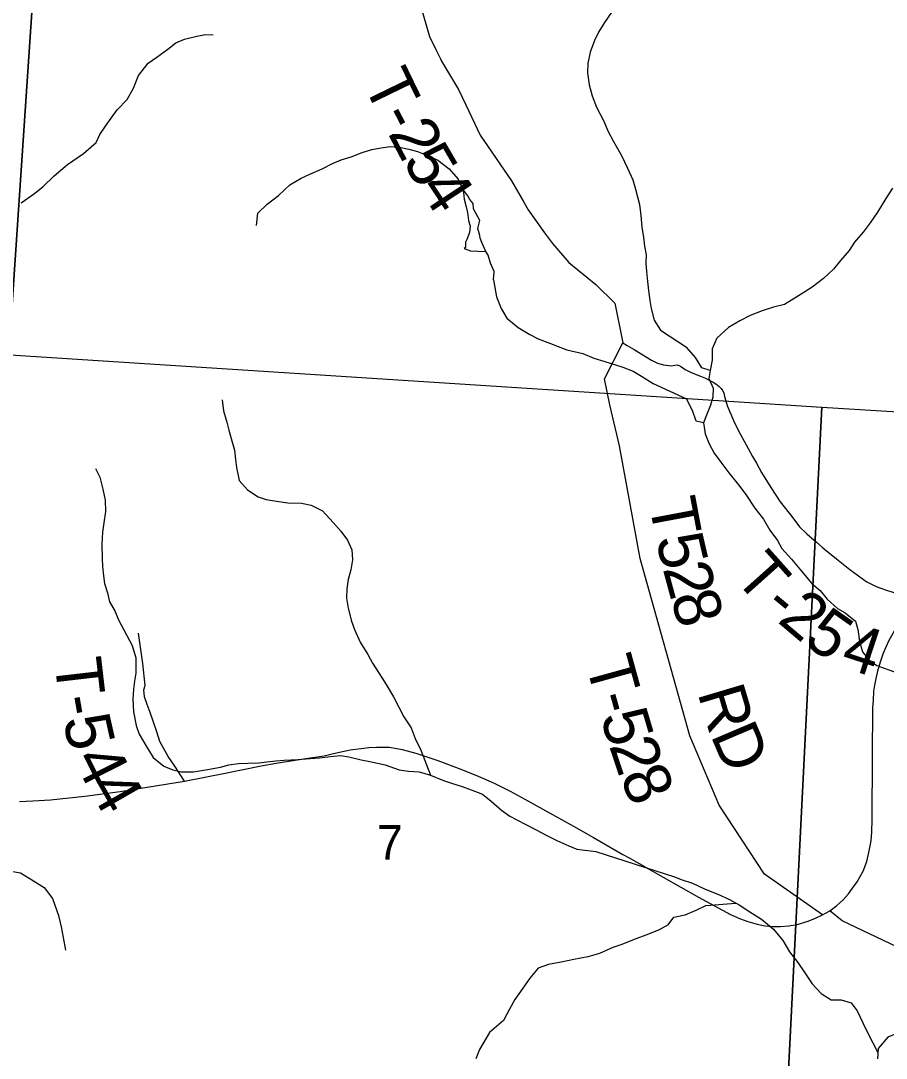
# Model space of a CAD drawing. Extents: x 0 to 44, y -23.8 to 22.
# Drawn here: x 3.565 to 4.614, y 18.843 to 20.101 of the extents above; entities that cross this region are included whole.
import ezdxf

# ---------------------------------------------------------------- set-up
doc = ezdxf.new("R2010")
doc.units = 0
for name, color, linetype in [('Default', 7, 'Continuous'), ('GM_X_Minor_Lake', 7, 'Continuous'), ('GM_X_Minor_River', 7, 'Continuous'), ('GM_X_Section', 7, 'Continuous'), ('GM_X_Section_Text', 7, 'Continuous'), ('GM_X_State_Route', 7, 'Continuous'), ('GM_X_Township_Road', 7, 'Continuous'), ('GM_X_Township_Road_Text', 7, 'Continuous'), ('SH_Cut_Line', 7, 'Continuous')]:
    doc.layers.add(name, color=color, linetype=linetype)

msp = doc.modelspace()

# ---------------------------------------------------------------- linework, layer by layer
at = {"layer": 'Default'}
msp.add_lwpolyline([(6.8158, 20.9), (2.3497, 20.9), (2.472, 20.6113), (2.8013, 19.8369), (3.0092, 19.3427), (3.0496, 19.2474), (3.1321, 19.0527), (3.1789, 18.9421), (3.455, 18.29), (3.5135, 19.1552), (3.5139, 19.1608), (3.5639, 19.9016), (3.5995, 20.4294), (3.5996, 20.4304), (3.6002, 20.4391), (3.6191, 20.7184), (3.9141, 20.6975), (4.3639, 20.6657), (6.7023, 20.5094), (6.7107, 20.5383)], close=True, dxfattribs=at)
msp.add_lwpolyline([(7.4495, 20.4611), (7.016, 20.4891), (6.892, 20.4972), (6.8124, 20.5023), (6.7257, 20.5079), (6.7023, 20.5094), (4.3639, 20.6657), (3.9141, 20.6975), (3.6191, 20.7184), (3.6002, 20.4391), (3.5996, 20.4304), (3.5995, 20.4294), (3.5639, 19.9016), (3.5139, 19.1608), (3.5135, 19.1552), (3.455, 18.29), (3.763, 17.5087), (3.7907, 17.4383), (4.026, 16.9163), (4.1422, 16.6361), (4.3476, 16.1408)], dxfattribs=at)
at = {"layer": 'GM_X_Minor_Lake'}
for points in [[(4.0999, 19.8977), (4.1014, 19.8927), (4.1025, 19.8844), (4.1047, 19.8753), (4.1066, 19.8684), (4.1076, 19.8586), (4.1095, 19.8517), (4.1087, 19.8442), (4.1056, 19.8355), (4.1041, 19.8324), (4.1041, 19.826), (4.1025, 19.8245), (4.1101, 19.8218), (4.1286, 19.8209)], [(4.1286, 19.8209), (4.1238, 19.832), (4.1219, 19.8373), (4.1215, 19.8403), (4.1189, 19.849), (4.1213, 19.8585), (4.1138, 19.8726), (4.1134, 19.8794), (4.1093, 19.884), (4.1067, 19.8885), (4.1018, 19.895), (4.0999, 19.8977)]]:
    msp.add_lwpolyline(points, dxfattribs=at)
at = {"layer": 'GM_X_Minor_River'}
for points in [[(4.2807, 20.1105), (4.2725, 20.0987), (4.2654, 20.0869), (4.2605, 20.0769), (4.255, 20.0625), (4.2524, 20.0491), (4.2518, 20.0378), (4.2538, 20.023), (4.2578, 20.0097), (4.2628, 19.9961), (4.2717, 19.9791), (4.2768, 19.9674), (4.2834, 19.9545), (4.293, 19.9375), (4.3004, 19.922), (4.307, 19.9081), (4.3101, 19.8967), (4.3149, 19.8778), (4.3165, 19.8645), (4.3178, 19.8505), (4.3198, 19.8379), (4.3211, 19.8273), (4.3231, 19.8171), (4.3228, 19.8068), (4.3236, 19.7966), (4.3249, 19.7845), (4.3261, 19.7738), (4.3274, 19.7617), (4.329, 19.7518), (4.333, 19.7378), (4.3403, 19.7258), (4.372, 19.7049)], [(3.5652, 19.8801), (3.5803, 19.8905), (3.5916, 19.8993), (3.6052, 19.9127), (3.6213, 19.9266), (3.6409, 19.94), (3.656, 19.9531), (3.6604, 19.963), (3.6676, 19.9729), (3.6743, 19.9825), (3.6818, 19.9928), (3.6938, 20.0055), (3.7013, 20.0192), (3.7076, 20.0344), (3.7192, 20.0494), (3.7297, 20.0567), (3.7429, 20.0663), (3.7527, 20.074), (3.7633, 20.0786), (3.7784, 20.0822), (3.7887, 20.0842), (3.7982, 20.0839)], [(3.8506, 19.8524), (3.8523, 19.8673), (3.8636, 19.8784), (3.8771, 19.8891), (3.8911, 19.9018), (3.9046, 19.9099), (3.9152, 19.9149), (3.93, 19.9212), (3.9428, 19.9277), (3.9534, 19.932), (3.9655, 19.9359), (3.9787, 19.941), (3.9905, 19.9445), (4.0041, 19.9473), (4.0136, 19.9485), (4.0257, 19.9471), (4.0352, 19.9449), (4.0459, 19.9424), (4.0581, 19.9376), (4.0703, 19.9316), (4.0844, 19.9211), (4.0952, 19.9087), (4.0999, 19.8977)], [(4.6219, 19.8977), (4.6139, 19.8852), (4.6035, 19.8689), (4.5947, 19.8557), (4.5862, 19.8443), (4.5759, 19.8322), (4.5693, 19.8224), (4.5586, 19.8099), (4.5502, 19.7994), (4.5383, 19.7884), (4.5246, 19.7779), (4.5143, 19.7711), (4.5047, 19.7651), (4.491, 19.7568), (4.4776, 19.7535), (4.4639, 19.7491), (4.4494, 19.7435), (4.4368, 19.7371), (4.4231, 19.7288), (4.4089, 19.716), (4.4032, 19.7028), (4.4031, 19.6891), (4.4007, 19.6769), (4.3908, 19.68), (4.3829, 19.6923), (4.372, 19.7049)], [(4.1381, 19.7868), (4.1387, 19.7966), (4.1342, 19.8069), (4.1313, 19.8164), (4.1286, 19.8209)], [(4.1381, 19.7868), (4.1394, 19.7774), (4.1418, 19.766), (4.1472, 19.752), (4.1542, 19.7403), (4.1679, 19.729), (4.1821, 19.7205), (4.192, 19.7152), (4.2069, 19.7093), (4.2164, 19.706), (4.227, 19.7019), (4.2461, 19.6975), (4.2598, 19.6916), (4.2731, 19.6875), (4.2845, 19.6842), (4.2948, 19.6809), (4.3074, 19.6761), (4.3173, 19.6697), (4.3314, 19.6611), (4.3719, 19.6422)], [(4.4007, 19.6769), (4.3991, 19.6671), (4.4044, 19.6552), (4.4039, 19.6442), (4.4012, 19.6347), (4.3961, 19.6226), (4.3927, 19.6131), (4.3945, 19.5998), (4.3993, 19.588), (4.4057, 19.5766), (4.4136, 19.5655), (4.4234, 19.5525), (4.4351, 19.538), (4.4438, 19.5265), (4.4547, 19.5097), (4.4653, 19.4963), (4.4732, 19.483), (4.4822, 19.4707), (4.4875, 19.4608), (4.4992, 19.4478), (4.5116, 19.4333), (4.524, 19.4184), (4.5339, 19.4099), (4.5425, 19.3996), (4.555, 19.3881), (4.5645, 19.3831), (4.577, 19.3728), (4.5799, 19.3629), (4.5817, 19.3484), (4.5855, 19.3358), (4.5926, 19.3263), (4.6028, 19.319), (4.6276, 19.3101)], [(3.809, 19.6413), (3.8107, 19.6277), (3.8146, 19.614), (3.817, 19.6042), (3.8197, 19.5944), (3.8237, 19.5803), (3.8253, 19.569), (3.8265, 19.5591), (3.8297, 19.5432), (3.8397, 19.5319), (3.8527, 19.5237), (3.8622, 19.5204), (3.8747, 19.5182), (3.8884, 19.5164), (3.9051, 19.5158), (3.9169, 19.5133), (3.9307, 19.5066), (3.9437, 19.4923), (3.9529, 19.4821), (3.961, 19.4712), (3.966, 19.4595), (3.9669, 19.4473), (3.9648, 19.4352), (3.9618, 19.4234), (3.9601, 19.412), (3.9598, 19.4009), (3.9618, 19.3884), (3.9658, 19.3729), (3.9693, 19.3627), (3.9763, 19.3472), (3.9855, 19.3325), (3.9913, 19.3219), (3.9994, 19.3095), (4.0079, 19.2962), (4.0168, 19.2811), (4.0233, 19.2687), (4.0292, 19.257), (4.038, 19.2434), (4.0431, 19.2305), (4.0497, 19.2165), (4.0617, 19.1863)], [(4.3927, 19.6131), (4.3836, 19.6155), (4.3791, 19.6284), (4.3719, 19.6422)], [(3.6554, 19.5579), (3.6604, 19.5473), (3.6643, 19.5329), (3.6671, 19.5196), (3.6673, 19.5056), (3.6655, 19.4919), (3.6637, 19.4809), (3.6631, 19.4661), (3.6636, 19.4486), (3.6637, 19.4391), (3.665, 19.4277), (3.6662, 19.4183), (3.6698, 19.4073), (3.6725, 19.3963), (3.6787, 19.3853), (3.6834, 19.3744), (3.6996, 19.3434), (3.7043, 19.3283), (3.7041, 19.3097), (3.7027, 19.3002), (3.7013, 19.2903), (3.7006, 19.2781), (3.7015, 19.2629), (3.7047, 19.2463), (3.7083, 19.2357), (3.7164, 19.2221), (3.7252, 19.2077), (3.7383, 19.1969), (3.7493, 19.1924), (3.7592, 19.1902), (3.774, 19.19), (3.7911, 19.1928), (3.807, 19.196), (3.8172, 19.1988), (3.8289, 19.2004), (3.8399, 19.2005), (3.8532, 19.201), (3.8631, 19.2022), (3.8741, 19.2035), (3.8843, 19.2043), (3.9006, 19.2052), (3.9158, 19.2065), (3.9268, 19.207), (3.9404, 19.2087), (3.9526, 19.2099), (3.9625, 19.2085), (3.9773, 19.2048), (3.9879, 19.2027), (4.0066, 19.1987), (4.0237, 19.1924), (4.0347, 19.191), (4.048, 19.1903), (4.0617, 19.1863), (4.0774, 19.1796), (4.0869, 19.1763), (4.0998, 19.1722), (4.1109, 19.1685), (4.1246, 19.163), (4.1353, 19.1547), (4.1475, 19.1438), (4.1579, 19.1363), (4.1762, 19.1266), (4.1899, 19.1199), (4.2025, 19.1128), (4.2147, 19.1069), (4.2292, 19.1006), (4.2391, 19.0965), (4.262, 19.0937), (4.3574, 19.0627)], [(3.5169, 19.0877), (3.5307, 19.0776), (3.5433, 19.0724), (3.5528, 19.0698), (3.5642, 19.0676), (3.5802, 19.0579), (3.5932, 19.0501), (3.6032, 19.0365), (3.6106, 19.0161), (3.6138, 19.0021), (3.6162, 18.9892), (3.619, 18.974)], [(4.3574, 19.0627), (4.3669, 19.0592), (4.3794, 19.055), (4.3946, 19.048), (4.4101, 19.0418), (4.4241, 19.0353), (4.4359, 19.0287), (4.4488, 19.0203), (4.4628, 19.0114), (4.4775, 18.9995), (4.4888, 18.9858), (4.4971, 18.972), (4.5069, 18.959), (4.5156, 18.9464), (4.5242, 18.9331), (4.5355, 18.9212), (4.5473, 18.9139), (4.5594, 18.9138), (4.5716, 18.9099), (4.5791, 18.9004), (4.5859, 18.8859), (4.5919, 18.8733), (4.6042, 18.8498)], [(4.3497, 19.0045), (4.3567, 19.0141), (4.3704, 19.0167), (4.3837, 19.0223), (4.3956, 19.0279), (4.4319, 19.0309)], [(4.3497, 19.0045), (4.3388, 18.9987), (4.3259, 18.9933), (4.3085, 18.9867), (4.2934, 18.9808), (4.2828, 18.977), (4.2666, 18.97), (4.2522, 18.966), (4.2355, 18.9625), (4.22, 18.9593), (4.2048, 18.9565), (4.192, 18.9522), (4.1822, 18.9399), (4.1736, 18.9277), (4.1639, 18.9143), (4.1575, 18.9025), (4.1501, 18.8887), (4.1331, 18.8742), (4.1208, 18.8535), (4.1164, 18.8421)], [(4.7208, 18.9693), (4.7307, 18.956), (4.7356, 18.9446), (4.7387, 18.9347), (4.7425, 18.9221), (4.7421, 18.9107), (4.7364, 18.8974), (4.7261, 18.8929), (4.7147, 18.8914), (4.7041, 18.8872), (4.6945, 18.88), (4.6847, 18.8743), (4.6744, 18.869), (4.6618, 18.8652), (4.6504, 18.8671), (4.6383, 18.8724), (4.628, 18.8732), (4.6162, 18.8686), (4.6045, 18.8546), (4.6037, 18.842)]]:
    msp.add_lwpolyline(points, dxfattribs=at)
at = {"layer": 'GM_X_Section'}
for points in [[(3.5517, 19.6956), (4.5363, 19.6324), (4.4853, 18.6191), (3.4822, 18.6631)], [(4.5363, 19.6324), (5.5628, 19.5693), (5.5009, 18.5537), (4.4853, 18.6191)]]:
    msp.add_lwpolyline(points, close=True, dxfattribs=at)
at = {"layer": 'GM_X_State_Route'}
for points in [[(4.6031, 19.3085), (4.604, 19.3127), (4.6072, 19.3236), (4.6106, 19.3334), (4.6143, 19.3418), (4.6179, 19.3498), (4.6244, 19.3611), (4.6327, 19.3729), (4.64, 19.383), (4.6511, 19.3961)], [(4.5368, 19.0166), (4.5457, 19.0217), (4.5545, 19.0282), (4.5618, 19.0351), (4.5684, 19.0423), (4.5735, 19.0489), (4.5791, 19.0567), (4.5862, 19.0698), (4.5906, 19.0813), (4.5933, 19.0922), (4.596, 19.1065), (4.5968, 19.1171), (4.5973, 19.1327), (4.5977, 19.2083), (4.5981, 19.2676), (4.5986, 19.2766), (4.5992, 19.288), (4.6004, 19.2953), (4.6019, 19.3032), (4.6031, 19.3085)], [(3.5631, 19.1543), (3.5795, 19.155), (3.6007, 19.1561), (3.6424, 19.1606), (3.6853, 19.1663), (3.7634, 19.179), (3.8126, 19.1887), (3.8563, 19.1976), (3.8746, 19.2006), (3.9129, 19.2066), (3.9327, 19.2097), (3.9438, 19.2124), (3.9567, 19.2153), (3.964, 19.2167), (3.9776, 19.2186), (3.9866, 19.2195), (3.9961, 19.2202), (4.0044, 19.2201), (4.0116, 19.2199), (4.0207, 19.2186), (4.0272, 19.2173), (4.0436, 19.2126), (4.0704, 19.2038), (4.0984, 19.1935), (4.1192, 19.185), (4.1389, 19.1763), (4.158, 19.1668), (4.1758, 19.1572), (4.2348, 19.1243), (4.2593, 19.1104)], [(4.2593, 19.1104), (4.2669, 19.1061), (4.2949, 19.09), (4.3024, 19.086), (4.3212, 19.0753), (4.3223, 19.0746), (4.3652, 19.0504), (4.3867, 19.0382), (4.406, 19.0275), (4.4255, 19.0171), (4.4361, 19.0124), (4.4465, 19.0085), (4.4576, 19.0053), (4.4675, 19.0034), (4.4761, 19.0028), (4.4859, 19.0025), (4.4963, 19.0033), (4.5063, 19.0051), (4.5195, 19.0089), (4.5286, 19.0126), (4.5368, 19.0166)], [(4.8438, 18.8255), (4.8327, 18.8461), (4.8199, 18.8657), (4.8086, 18.8788), (4.8054, 18.8821), (4.8065, 18.8832), (4.8014, 18.888), (4.794, 18.8948), (4.7879, 18.9002), (4.7729, 18.9104), (4.7657, 18.9146), (4.7574, 18.919), (4.7568, 18.9181), (4.7403, 18.9264), (4.6603, 18.9624), (4.5608, 19.0096), (4.5457, 19.0217)]]:
    msp.add_lwpolyline(points, dxfattribs=at)
at = {"layer": 'GM_X_Township_Road'}
for points in [[(3.9686, 20.2538), (3.9691, 20.2449), (3.9768, 20.2107), (3.9894, 20.1806), (4.0051, 20.1585), (4.0209, 20.1462), (4.0394, 20.1316), (4.0502, 20.1163), (4.0605, 20.0816), (4.0685, 20.0651), (4.0736, 20.0547)], [(4.0736, 20.0547), (4.0751, 20.0517), (4.0955, 20.0174), (4.1043, 19.9988), (4.1218, 19.9619), (4.1597, 19.9065), (4.1746, 19.881), (4.1802, 19.8714), (4.1999, 19.8438)], [(4.1999, 19.8438), (4.2094, 19.8306), (4.2295, 19.8075), (4.2619, 19.7809), (4.2852, 19.7583), (4.2936, 19.7163)], [(4.2936, 19.7163), (4.2948, 19.7103), (4.3002, 19.7071), (4.3086, 19.702), (4.3223, 19.6938), (4.3296, 19.6891), (4.3367, 19.6858), (4.3442, 19.6837), (4.3538, 19.6825), (4.3578, 19.6832), (4.3607, 19.6837), (4.3647, 19.682), (4.3703, 19.678), (4.3776, 19.6743), (4.3891, 19.67), (4.3952, 19.6674), (4.402, 19.664), (4.4044, 19.6625), (4.4077, 19.6604), (4.4116, 19.6574), (4.4139, 19.6551), (4.4158, 19.6526), (4.4171, 19.6497), (4.4182, 19.6454), (4.4199, 19.6398), (4.4215, 19.6341), (4.4243, 19.6276), (4.4261, 19.623), (4.429, 19.6162), (4.4335, 19.6067), (4.4376, 19.5991), (4.4419, 19.5911), (4.4467, 19.582), (4.4522, 19.5725), (4.4567, 19.5644), (4.4628, 19.5529), (4.4741, 19.535), (4.4854, 19.5176), (4.4996, 19.4998), (4.5091, 19.4872), (4.5174, 19.4791)], [(4.5368, 19.0166), (4.4667, 19.0659), (4.4116, 19.1498), (4.3762, 19.2338), (4.3159, 19.4489), (4.2909, 19.5853), (4.2791, 19.6351), (4.2726, 19.6666), (4.2948, 19.7103)], [(4.5174, 19.4791), (4.5178, 19.4786), (4.5295, 19.4684), (4.5365, 19.4627), (4.5419, 19.4582), (4.5473, 19.4537), (4.5538, 19.4485), (4.5618, 19.442), (4.5702, 19.4355), (4.579, 19.4288), (4.5866, 19.4234), (4.5908, 19.4205), (4.5965, 19.4175), (4.602, 19.415), (4.6078, 19.413), (4.6147, 19.4106), (4.6223, 19.408), (4.6291, 19.4058), (4.6341, 19.404), (4.6428, 19.4003), (4.6511, 19.3961)], [(3.7634, 19.179), (3.7517, 19.1972), (3.7434, 19.2088), (3.7333, 19.227), (3.7298, 19.2385), (3.7216, 19.2622), (3.7181, 19.2716), (3.7147, 19.2811), (3.7139, 19.2894), (3.7156, 19.2948), (3.7127, 19.3213), (3.7076, 19.3583)]]:
    msp.add_lwpolyline(points, dxfattribs=at)
at = {"layer": 'SH_Cut_Line'}
for points in [[(4.3476, 16.1408), (4.1422, 16.6361), (4.026, 16.9163), (3.7907, 17.4383), (3.763, 17.5087), (3.455, 18.29), (3.5135, 19.1552), (3.5139, 19.1608), (3.5639, 19.9016), (3.5995, 20.4294), (3.5996, 20.4304), (3.6002, 20.4391), (3.6191, 20.7184), (3.9141, 20.6975), (4.3639, 20.6657), (6.7023, 20.5094), (6.7107, 20.5383), (6.8158, 20.9), (2.1, 20.9), (2.1, 14.1)], [(8.9, 20.9), (6.8158, 20.9), (6.7107, 20.5383), (6.7023, 20.5094), (4.3639, 20.6657), (3.9141, 20.6975), (3.6191, 20.7184), (3.6002, 20.4391), (3.5996, 20.4304), (3.5995, 20.4294), (3.5639, 19.9016), (3.5139, 19.1608), (3.5135, 19.1552), (3.455, 18.29), (3.763, 17.5087), (3.7907, 17.4383), (4.026, 16.9163), (4.1422, 16.6361), (4.3476, 16.1408)]]:
    msp.add_lwpolyline(points, dxfattribs=at)

# ---------------------------------------------------------------- texts
at = {"layer": 'GM_X_Section_Text'}
msp.add_text('7', height=0.0419, rotation=0, dxfattribs=at).set_placement((3.9968, 19.0836))
at = {"layer": 'GM_X_Township_Road_Text'}
for s, rotation, p in [('T', 295.8962, (3.9792, 20.0251)), ('-', 297.3992, (3.9985, 19.9854)), ('2', 297.627, (4.0094, 19.9644)), ('5', 300.2666, (4.027, 19.9309)), ('4', 303.3891, (4.0464, 19.8978)), ('T', 280.6686, (4.3262, 19.5173)), ('5', 283.0271, (4.3346, 19.4731)), ('T', 311.7602, (4.4281, 19.4254)), ('2', 285.1778, (4.343, 19.4367)), ('8', 285.793, (4.3524, 19.4023)), ('-', 320.4125, (4.4632, 19.3872)), ('2', 319.804, (4.481, 19.3725)), ('5', 325.0392, (4.5123, 19.3464)), ('4', 341.7068, (4.557, 19.3183)), ('T', 285.4209, (4.2493, 19.3223)), ('T', 276.6102, (3.6054, 19.3256)), ('R', 286.5802, (4.3851, 19.2861)), ('-', 285.6819, (4.2606, 19.281)), ('-', 279.9174, (3.6108, 19.2798)), ('5', 282.7578, (3.6155, 19.2538)), ('5', 286.5848, (4.2672, 19.2576)), ('D', 293.0641, (4.4007, 19.2349)), ('2', 288.55, (4.2778, 19.2221)), ('4', 296.8618, (3.6283, 19.2054)), ('8', 292.9138, (4.2906, 19.1845)), ('4', 299.8129, (3.6457, 19.1713))]:
    msp.add_text(s, height=0.0568, rotation=rotation, dxfattribs=at).set_placement(p)

doc.saveas('drawing.dxf')
